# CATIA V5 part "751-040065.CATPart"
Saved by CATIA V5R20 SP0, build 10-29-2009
Part number: 751-040065
Source: Unknown
Property "A": "40.000"
Property "ARTICLENO": "751-040065"
Property "BOMINFO": "751-040065"
Property "CODE": "751-040065"
Property "D1": "35.000"
Property "D2": "30.000"
Property "D3": "34.000"
Property "D4": "27.000"
Property "L": "65.000"
Property "L1": "45.000"
Property "LINA": "751-040065"
Property "MAXFORCE": "5200 N"
Property "NB": "751-040065"
Property "NBSYN": "$CODE."
Property "NN": "751"
Property "NT": "Slide Stop Block"
Property "SUPPLIER": "CF"
Property "W": "60.000"
Bounding box of the stored display mesh (mm): x 0 to 45, y 0 to 60, z -32.5 to 32.5
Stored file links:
  C:\Users\Utente\Desktop\3D files 751\751-040065.CATPart
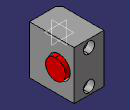
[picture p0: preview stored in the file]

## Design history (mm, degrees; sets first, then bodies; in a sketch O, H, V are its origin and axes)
Body1 "Geometry.1" (main body)
  Solid1 "751-040065.catpart": solid without history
